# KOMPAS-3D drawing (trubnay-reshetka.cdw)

Views: Вид 1, Вид 2, Вид 3, Вид 4, Вид 5, Выносной элемент А, Выносной элемент, Выносной элемент Б
Referenced files: Трубная решётка 2.cdw
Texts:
  Трубная решётка
  Инженер-конструктор
  Химстроймонтаж
  -граница отверстий
  obafgkm
  Сталь 10Х17Н13М2Т ГОСТ 5632-72
Dimensions and other numbers on the sheet: 5; 3; 7; 0,5; 1; 9 ряд - 7 отв.; 8 ряд - 10 отв.; 7 ряд - 13 отв.; 6 ряд - 14 отв.; 5 ряд - 15 отв.; 3 ряд - 15 отв.; 2 ряд - 16 отв.; 1 ряд - 17 отв.; 596; 612; 590; 2; 45; 8; 10х1; 18; 32; -214отв; 25,35; 1:5; 67; 0; 4; 6; 9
